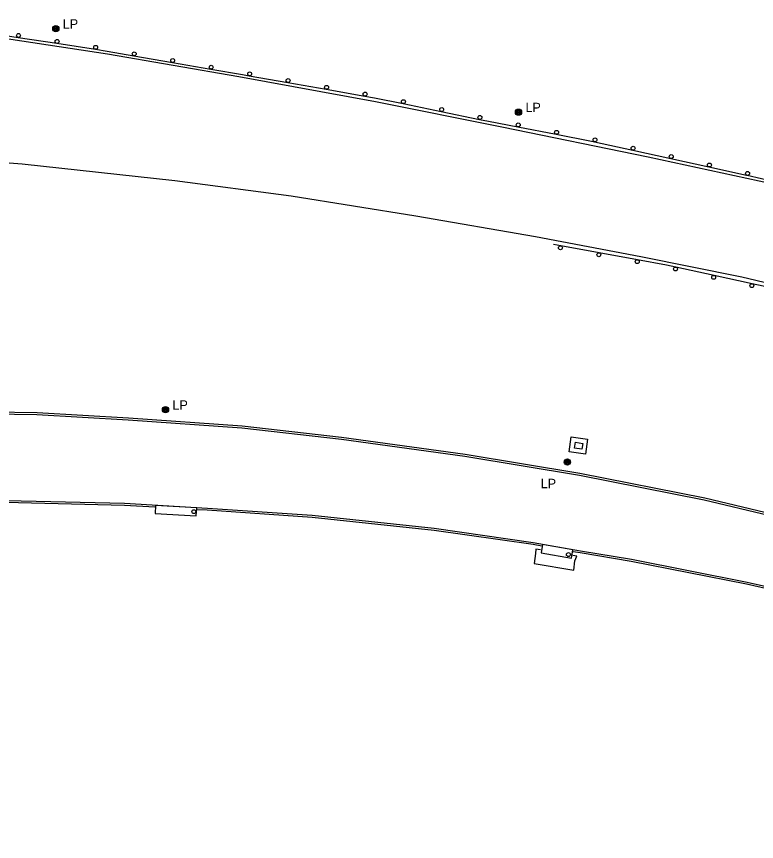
# Model space of a CAD drawing. Extents: x 2402803 to 2427059, y 6985292 to 6997652.
# Drawn here: x 2413532.1 to 2413911, y 6991185.9 to 6991608.5 of the extents above; entities that cross this region are included whole.
import ezdxf

# ---------------------------------------------------------------- set-up
doc = ezdxf.new("R2010")
doc.units = 0
for name, color, linetype in [('p_drainage conc drain', 7, 'Continuous'), ('p_road - paved curb', 7, 'Continuous'), ('p_road bridge end', 7, 'Continuous'), ('p_road guard rails', 7, 'Continuous'), ('p_structure general', 7, 'Continuous'), ('p_utility manhole', 7, 'Continuous')]:
    doc.layers.add(name, color=color, linetype=linetype)

msp = doc.modelspace()

# ---------------------------------------------------------------- linework, layer by layer
at = {"layer": 'p_drainage conc drain'}
msp.add_lwpolyline([(2413816.13, 6991393.19), (2413824.52, 6991391.99), (2413823.42, 6991384.31), (2413815.03, 6991385.51)], close=True, dxfattribs=at)
msp.add_lwpolyline([(2413800.33, 6991335.29), (2413797.97, 6991335.65), (2413797.79, 6991333.49), (2413797.11, 6991328.3), (2413817.39, 6991324.92), (2413818.04, 6991329.67), (2413818.97, 6991332.08), (2413817, 6991332.47)], dxfattribs=at)
at = {"layer": 'p_road - paved curb'}
for points in [[(2413453.34, 6991608.46), (2413509.85, 6991599.67), (2413578.7, 6991589.29), (2413645.86, 6991577.8), (2413715.9, 6991564.99), (2413780.65, 6991551.96), (2413855.53, 6991536.52), (2413918.66, 6991522.88), (2413985.54, 6991507.12), (2414047.19, 6991492.25), (2414109.4, 6991475.44), (2414161.57, 6991461.23), (2414212.88, 6991446.72), (2414244.43, 6991437.52)], [(2414245.83, 6991384.24), (2414224.52, 6991391.1), (2414175.69, 6991405.24), (2414127.62, 6991418.9), (2414068.94, 6991434.75), (2414009.43, 6991449.6), (2413956.34, 6991462.24), (2413903.4, 6991474.96), (2413851.74, 6991485.33), (2413797.83, 6991495.68), (2413736.61, 6991506.25), (2413672.73, 6991516.4), (2413613.14, 6991524.23), (2413535.08, 6991532.86), (2413481.44, 6991537), (2413453.89, 6991539.47)], [(2413454.02, 6991406.53), (2413496.39, 6991406.37), (2413542.63, 6991405.58), (2413589.38, 6991402.88), (2413647.61, 6991398.85), (2413698.58, 6991392.94), (2413761.8, 6991384.22), (2413820.56, 6991374.6), (2413884.46, 6991361.97), (2413950.32, 6991346.15), (2414009.68, 6991330.33), (2414061.69, 6991314.17), (2414124.33, 6991294.84), (2414180.4, 6991277.52), (2414240.81, 6991258.42), (2414302.17, 6991239.11)], [(2413454.02, 6991405.53), (2413496.38, 6991405.37), (2413542.59, 6991404.58), (2413589.32, 6991401.88), (2413647.52, 6991397.85), (2413698.45, 6991391.95), (2413761.65, 6991383.23), (2413820.38, 6991373.62), (2413884.25, 6991360.99), (2413950.07, 6991345.18), (2414009.4, 6991329.37), (2414061.39, 6991313.21), (2414124.04, 6991293.88), (2414180.1, 6991276.57), (2414240.51, 6991257.47), (2414301.87, 6991238.16)], [(2414277.03, 6991186.65), (2414260.39, 6991202.15), (2414237.15, 6991218.35), (2414211.46, 6991231.59), (2414191.18, 6991238.74), (2414137.57, 6991255.4), (2414085.36, 6991271.45), (2414038.86, 6991284.99), (2413995.91, 6991297.26), (2413956.43, 6991307.23), (2413906.16, 6991318.65), (2413847, 6991330.36), (2413820.95, 6991334.68), (2413796.72, 6991338.96), (2413745.99, 6991346.15), (2413683.54, 6991352.92), (2413629.83, 6991356.54), (2413587.38, 6991358.99), (2413519.22, 6991360.65), (2413455.96, 6991360.73)], [(2413602.93, 6991357.09), (2413587.34, 6991357.99), (2413519.21, 6991359.65), (2413455.96, 6991359.73)], [(2413801.15, 6991337.16), (2413796.56, 6991337.97), (2413745.87, 6991345.16), (2413683.45, 6991351.92), (2413629.77, 6991355.54), (2413624.57, 6991355.84)], [(2414276.35, 6991185.92), (2414259.76, 6991201.37), (2414236.63, 6991217.49), (2414211.06, 6991230.67), (2414190.87, 6991237.79), (2414137.27, 6991254.44), (2414085.07, 6991270.49), (2414038.58, 6991284.03), (2413995.65, 6991296.29), (2413956.2, 6991306.26), (2413905.95, 6991317.67), (2413846.82, 6991329.38), (2413820.78, 6991333.69), (2413817.11, 6991334.34)]]:
    msp.add_lwpolyline(points, dxfattribs=at)
at = {"layer": 'p_road bridge end'}
for points in [[(2413818.31, 6991390.37), (2413822.05, 6991389.78), (2413821.59, 6991386.84), (2413817.85, 6991387.43)], [(2413624.41, 6991356.75), (2413603.31, 6991357.97), (2413603.07, 6991353.86), (2413624.17, 6991352.64)], [(2413816.97, 6991335.28), (2413801.46, 6991338.02), (2413800.7, 6991333.73), (2413816.21, 6991330.99)]]:
    msp.add_lwpolyline(points, close=True, dxfattribs=at)
at = {"layer": 'p_road guard rails'}
for p, q in [((2413532.96, 6991597.77), (2413552.73, 6991594.72)), ((2413552.73, 6991594.72), (2413572.49, 6991591.67)), ((2413592.21, 6991588.37), (2413611.91, 6991584.95)), ((2413611.91, 6991584.95), (2413631.6, 6991581.53)), ((2413651.3, 6991578.11), (2413671, 6991574.65)), ((2413671, 6991574.65), (2413690.7, 6991571.19)), ((2413690.7, 6991571.19), (2413710.4, 6991567.73)), ((2413730.01, 6991563.85), (2413749.6, 6991559.82)), ((2413749.6, 6991559.82), (2413769.19, 6991555.79)), ((2413788.82, 6991551.94), (2413808.45, 6991548.15)), ((2413828.07, 6991544.32), (2413847.6, 6991540.02)), ((2413847.6, 6991540.02), (2413867.13, 6991535.72)), ((2413867.13, 6991535.72), (2413886.66, 6991531.42)), ((2413906.19, 6991527.12), (2413925.66, 6991522.58)), ((2413810.76, 6991490.99), (2413807, 6991491.67)), ((2413830.43, 6991487.43), (2413810.76, 6991490.99)), ((2413850.1, 6991483.86), (2413830.43, 6991487.43)), ((2413889.28, 6991475.86), (2413869.74, 6991480.13)), ((2413908.82, 6991471.6), (2413889.28, 6991475.86)), ((2413928.36, 6991467.34), (2413908.82, 6991471.6))]:
    msp.add_line(p, q, dxfattribs=at)
for points in [[(2413513.2, 6991600.81), (2413514.41, 6991600.63), (2413532.96, 6991597.77)], [(2413572.49, 6991591.67), (2413578.57, 6991590.73), (2413592.21, 6991588.37)], [(2413631.6, 6991581.53), (2413647.84, 6991578.72), (2413651.3, 6991578.11)], [(2413710.4, 6991567.73), (2413715.32, 6991566.87), (2413730.01, 6991563.85)], [(2413769.19, 6991555.79), (2413773.8, 6991554.84), (2413788.82, 6991551.94)], [(2413808.45, 6991548.15), (2413826.49, 6991544.67), (2413828.07, 6991544.32)], [(2413886.66, 6991531.42), (2413905.92, 6991527.18), (2413906.19, 6991527.12)], [(2413869.74, 6991480.13), (2413864.91, 6991481.18), (2413850.1, 6991483.86)]]:
    msp.add_lwpolyline(points, dxfattribs=at)
for centre in [(2413533.11, 6991598.76), (2413552.88, 6991595.71), (2413572.64, 6991592.66), (2413592.38, 6991589.35), (2413612.08, 6991585.94), (2413631.77, 6991582.52), (2413651.48, 6991579.1), (2413671.17, 6991575.64), (2413690.87, 6991572.18), (2413710.57, 6991568.72), (2413730.21, 6991564.83), (2413749.8, 6991560.8), (2413769.39, 6991556.77), (2413789.01, 6991552.92), (2413808.64, 6991549.13), (2413828.29, 6991545.3), (2413847.82, 6991541), (2413867.35, 6991536.7), (2413886.87, 6991532.4), (2413906.41, 6991528.09), (2413810.58, 6991490), (2413830.25, 6991486.44), (2413849.92, 6991482.88), (2413869.52, 6991479.15), (2413889.06, 6991474.89), (2413908.6, 6991470.62)]:
    msp.add_circle(centre, 1, dxfattribs=at)
at = {"layer": 'p_structure general'}
for centre in [(2413622.88, 6991354.86), (2413814.7, 6991332.86)]:
    msp.add_circle(centre, 1, dxfattribs=at)
at = {"layer": 'p_utility manhole'}
for centre, radius in [((2413552.22, 6991602.27), 1.6), ((2413552.22, 6991602.27), 1.3), ((2413552.22, 6991602.27), 1), ((2413552.22, 6991602.27), 0.539), ((2413552.22, 6991602.27), 0.192), ((2413789.14, 6991559.47), 1.6), ((2413789.14, 6991559.47), 1.3), ((2413789.14, 6991559.47), 1), ((2413789.14, 6991559.47), 0.539), ((2413789.14, 6991559.47), 0.192), ((2413608.39, 6991407.06), 1.6), ((2413608.39, 6991407.06), 1.3), ((2413608.39, 6991407.06), 1), ((2413608.39, 6991407.06), 0.539), ((2413608.39, 6991407.06), 0.192), ((2413814.19, 6991380.26), 1.6), ((2413814.19, 6991380.26), 1.3), ((2413814.19, 6991380.26), 1), ((2413814.19, 6991380.26), 0.539), ((2413814.19, 6991380.26), 0.192)]:
    msp.add_circle(centre, radius, dxfattribs=at)

# ---------------------------------------------------------------- texts
for p in [(2413552.22, 6991602.27), (2413789.14, 6991559.47), (2413608.39, 6991407.06), (2413796.94, 6991366.88)]:
    msp.add_text('  LP', height=4.8, dxfattribs=at).set_placement(p)

doc.saveas('drawing.dxf')
